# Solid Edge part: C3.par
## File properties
Author: edge
Template: Jis Part.par
Last saved by: edge
Revision: 4
Application: Solid Edge
Username: edge
文書内容のタイプ: 0
Accuracy: 0.990
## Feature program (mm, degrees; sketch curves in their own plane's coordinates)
sketch for "unnamed Protrusion 1" plane through (0, 0, 0) normal (0, 0, 1) x-axis (1, 0, 0)
  line (75, -40) -> (-75, -40)
  line (-75, -40) -> (-75, 40)
  line (-75, 40) -> (75, 40)
  line (75, 40) -> (75, -40)
  dimension (linear) = 75
  dimension (linear) = 75
extrude "unnamed Protrusion 1" add finite 30 along +normal
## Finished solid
Body 1: solid body, 6 faces, 12 edges, 8 vertices.
  Faces by surface: plane 6
  Edges by curve: line 12
Bounding box of the edges (mm): 150.000 x 80.000 x 30.000, from (-75, -40, 0) to (75, 40, 30).
Planar faces by outward normal: +x 1, +y 1, +z 1, -x 1, -y 1, -z 1
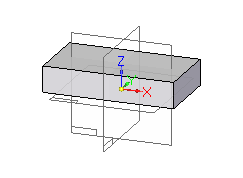
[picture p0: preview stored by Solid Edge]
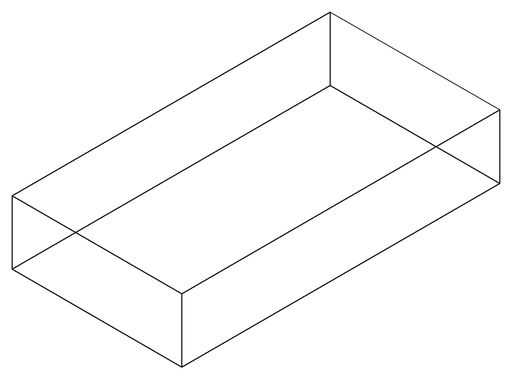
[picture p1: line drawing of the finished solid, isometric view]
